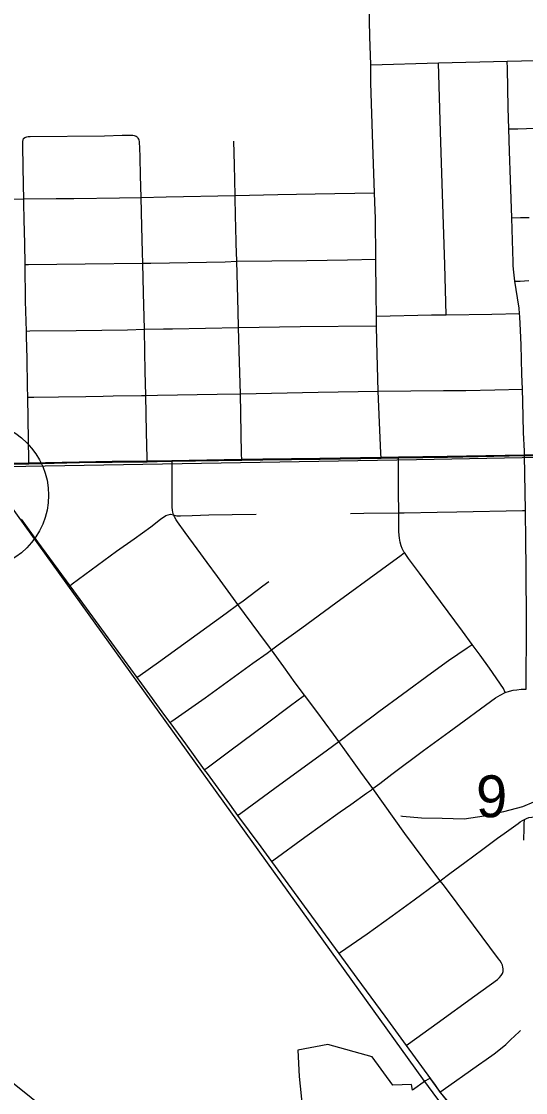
# Model space of a CAD drawing. Extents: x -6.4 to 34, y -4.2 to 22.
# Drawn here: x 3.551 to 4.056, y 15.21 to 16.282 of the extents above; entities that cross this region are included whole.
import ezdxf

# ---------------------------------------------------------------- set-up
doc = ezdxf.new("R2010")
doc.units = 0
for name, color, linetype in [('GM_X_Corporation', 7, 'Continuous'), ('GM_X_County_Road', 7, 'Continuous'), ('GM_X_Minor_River', 7, 'Continuous'), ('GM_X_Rail_Line', 7, 'Continuous'), ('GM_X_Section_Text', 7, 'Continuous'), ('GM_X_State_Route', 7, 'Continuous'), ('GM_X_Township_Road', 7, 'Continuous'), ('GM_X_Unincorporated', 7, 'Continuous')]:
    doc.layers.add(name, color=color, linetype=linetype)

msp = doc.modelspace()

# ---------------------------------------------------------------- linework, layer by layer
at = {"layer": 'GM_X_Corporation'}
msp.add_lwpolyline([(3.9465, 15.8436), (4.8102, 15.8601), (4.8285, 15.2133), (4.4185, 15.2024), (4.0324, 15.1921), (3.7019, 15.1869), (3.3086, 15.1812), (3.2389, 15.1802), (3.2231, 15.8313)], close=True, dxfattribs=at)
for points in [[(4.0637, 15.8482), (4.0545, 15.848), (3.9774, 15.8466), (3.9286, 15.8458), (3.911, 15.8456), (3.8501, 15.8447), (3.7928, 15.8438), (3.7716, 15.8435), (3.7019, 15.8423), (3.6872, 15.8421), (3.6771, 15.842), (3.6422, 15.8417), (3.6093, 15.8411), (3.5587, 15.84), (3.5102, 15.839)], [(3.5102, 15.839), (3.5587, 15.84), (3.6093, 15.8411), (3.6422, 15.8417), (3.6771, 15.842), (3.6872, 15.8421), (3.7019, 15.8423), (3.7716, 15.8435), (3.7928, 15.8438), (3.8501, 15.8447), (3.911, 15.8456), (3.9286, 15.8458), (3.9774, 15.8466), (4.0545, 15.848), (4.0637, 15.8482)], [(3.9773, 15.2021), (3.9699, 15.2114), (3.9604, 15.2247), (3.9558, 15.222), (3.9426, 15.2128), (3.9415, 15.2183), (3.9228, 15.2178), (3.9022, 15.2461), (3.8579, 15.2584), (3.828, 15.2527), (3.8293, 15.2262), (3.8325, 15.1939)]]:
    msp.add_lwpolyline(points, dxfattribs=at)
at = {"layer": 'GM_X_County_Road'}
msp.add_lwpolyline([(3.5104, 15.8384), (3.5589, 15.8394), (3.6095, 15.8405), (3.6424, 15.8411), (3.6773, 15.8414), (3.6874, 15.8415), (3.7021, 15.8418), (3.7718, 15.8429), (3.793, 15.8433), (3.8503, 15.8441), (3.9112, 15.845), (3.9288, 15.8453), (3.9776, 15.846), (4.0547, 15.8475), (4.0639, 15.8477), (4.1199, 15.8487)], dxfattribs=at)
at = {"layer": 'GM_X_Minor_River'}
msp.add_lwpolyline([(4.0745, 15.5053), (4.0528, 15.4961), (4.0335, 15.4911), (4.0143, 15.4869), (3.9943, 15.4838), (3.9723, 15.4845), (3.9518, 15.4848), (3.9325, 15.4863), (3.931, 15.4867)], dxfattribs=at)
at = {"layer": 'GM_X_Rail_Line'}
for points in [[(3.9386, 14.884), (3.8593, 14.9547), (3.8412, 14.9757), (3.7101, 15.0851), (3.4966, 15.2567), (3.3676, 15.3664), (3.3218, 15.4134), (3.2936, 15.4451), (3.262, 15.4819), (3.2273, 15.5333), (3.0474, 15.8446), (2.8972, 16.1027), (2.8207, 16.2287), (2.6643, 16.5111), (2.602, 16.6246), (2.5066, 16.7881), (2.4417, 16.9006), (2.4184, 16.9355), (2.3897, 16.999), (2.3745, 17.0469), (2.3628, 17.1053), (2.3468, 17.2127), (2.3318, 17.3221), (2.3038, 17.4809)], [(2.3038, 17.4809), (2.7191, 16.9064), (3.0546, 16.4509), (3.5178, 15.8282), (3.9525, 15.2239), (4.2793, 14.7815), (4.2857, 14.7721), (4.2939, 14.7539), (4.295, 14.5937)]]:
    msp.add_lwpolyline(points, dxfattribs=at)
at = {"layer": 'GM_X_State_Route'}
for points in [[(3.5511, 15.7838), (3.5676, 15.7612), (3.5998, 15.7173), (3.629, 15.6775), (3.667, 15.6254), (3.6715, 15.6192), (3.6946, 15.5876), (3.6999, 15.5804), (3.7156, 15.559), (3.7344, 15.5332), (3.7372, 15.5293), (3.7596, 15.4988), (3.7677, 15.4876), (3.7908, 15.4561), (3.8016, 15.4414), (3.8378, 15.3918), (3.8689, 15.3494), (3.8871, 15.3247), (3.9151, 15.2866), (3.9364, 15.2573), (3.9606, 15.2241)], [(3.9606, 15.2241), (3.9652, 15.2177), (3.9701, 15.2108), (3.9775, 15.2015)]]:
    msp.add_lwpolyline(points, dxfattribs=at)
at = {"layer": 'GM_X_Township_Road'}
msp.add_line((3.9067, 15.9775), (3.9066, 15.9871), dxfattribs=at)
for points in [[(3.9066, 15.9871), (3.9064, 16.0085), (3.9059, 16.044), (3.9055, 16.0855), (3.9053, 16.0923), (3.9047, 16.1104), (3.9044, 16.1202), (3.903, 16.1587), (3.901, 16.2204), (3.9008, 16.2386), (3.9001, 16.2669), (3.8989, 16.3134), (3.898, 16.347), (3.8977, 16.3644), (3.8972, 16.3921), (3.8969, 16.4085), (3.8965, 16.4331)], [(3.9008, 16.2386), (3.9688, 16.2404), (4.0374, 16.2421), (4.0949, 16.2434)], [(3.9762, 15.9884), (3.9751, 16.0385), (3.9725, 16.1093), (3.9708, 16.1715), (3.9688, 16.2404)], [(4.0496, 15.9898), (4.0492, 15.9949), (4.0476, 16.0054), (4.045, 16.0219), (4.0436, 16.0341), (4.0434, 16.0378), (4.0433, 16.0415), (4.0427, 16.0626), (4.042, 16.0855), (4.0406, 16.1235), (4.0397, 16.1521), (4.039, 16.1743), (4.0384, 16.1956), (4.0376, 16.2348), (4.0374, 16.2421)], [(4.039, 16.1743), (4.0481, 16.1746), (4.0654, 16.1751), (4.0826, 16.1757)], [(3.5589, 15.8394), (3.5589, 15.8426), (3.5583, 15.8844), (3.5579, 15.9059), (3.5577, 15.9166), (3.5571, 15.9448), (3.5566, 15.9668), (3.5564, 15.9721), (3.5556, 16.0021), (3.5551, 16.0387), (3.5548, 16.0596), (3.5543, 16.0835), (3.5539, 16.1001), (3.5538, 16.1043), (3.5534, 16.1182), (3.5528, 16.1563), (3.5529, 16.1618), (3.5531, 16.1636), (3.5536, 16.1649), (3.5549, 16.1659)], [(3.5549, 16.1659), (3.5569, 16.1666), (3.5583, 16.1669), (3.5602, 16.1668), (3.6346, 16.1676), (3.6522, 16.1681), (3.6591, 16.1682), (3.6613, 16.1682), (3.6629, 16.1681), (3.6641, 16.1679), (3.6652, 16.1676), (3.6663, 16.1672), (3.6671, 16.1666)], [(3.6773, 15.8414), (3.6773, 15.8448), (3.6767, 15.8711), (3.676, 15.9078), (3.6754, 15.9321), (3.675, 15.9512), (3.6745, 15.974), (3.6737, 16.0105), (3.6728, 16.04), (3.6726, 16.0507), (3.672, 16.0767), (3.6712, 16.1058), (3.6707, 16.1276), (3.6703, 16.1459), (3.6699, 16.1559), (3.6696, 16.1603), (3.6695, 16.1618), (3.6692, 16.1631), (3.6688, 16.1642), (3.6682, 16.1652), (3.6677, 16.1659), (3.6671, 16.1666)], [(3.7657, 16.0859), (3.7652, 16.1078), (3.7645, 16.1384), (3.7639, 16.1621)], [(3.3737, 16.1144), (3.381, 16.1107), (3.3882, 16.1072), (3.3921, 16.1056), (3.3974, 16.104), (3.4039, 16.1025), (3.4087, 16.1017), (3.4142, 16.1014), (3.4204, 16.1014), (3.4322, 16.1014), (3.4569, 16.102), (3.4797, 16.1026), (3.507, 16.1036), (3.5349, 16.1041), (3.5538, 16.1043), (3.5862, 16.1047), (3.6039, 16.1049), (3.6497, 16.1054), (3.6712, 16.1058), (3.6962, 16.1063), (3.7652, 16.1078), (3.8079, 16.1088), (3.8452, 16.1093), (3.9047, 16.1104)], [(3.7718, 15.8429), (3.7717, 15.8497), (3.7705, 15.9092), (3.7697, 15.941), (3.7687, 15.9756), (3.7682, 15.992), (3.7669, 16.0419), (3.7664, 16.0596), (3.7659, 16.077), (3.7657, 16.0859)], [(4.042, 16.0855), (4.0508, 16.0856), (4.0594, 16.0857)], [(3.5551, 16.0387), (3.5587, 16.0388), (3.6152, 16.0395), (3.6728, 16.04), (3.681, 16.0402), (3.7551, 16.0415), (3.7669, 16.0419), (3.8371, 16.0428), (3.8775, 16.0435), (3.9059, 16.044)], [(4.045, 16.0219), (4.0504, 16.0222), (4.059, 16.0227)], [(3.9066, 15.9871), (3.9616, 15.9882), (3.9762, 15.9884), (4.0219, 15.989), (4.0496, 15.9898)], [(4.0547, 15.8475), (4.0545, 15.8519), (4.0535, 15.8707), (4.0529, 15.9018), (4.0525, 15.9139), (4.052, 15.9291), (4.0513, 15.9583), (4.0508, 15.9726), (4.0499, 15.9863), (4.0496, 15.9898)], [(3.5564, 15.9721), (3.5598, 15.9722), (3.6063, 15.9728), (3.6576, 15.9735), (3.6745, 15.974), (3.6936, 15.9743)], [(3.6936, 15.9743), (3.7026, 15.9744), (3.7687, 15.9756), (3.8303, 15.9768), (3.9067, 15.9775)], [(3.9112, 15.845), (3.911, 15.8501), (3.9096, 15.8808), (3.9084, 15.9119), (3.9076, 15.937), (3.9069, 15.9617), (3.9067, 15.9775)], [(3.5579, 15.9059), (3.5639, 15.906), (3.5885, 15.9063), (3.6158, 15.9067), (3.6332, 15.9071), (3.6431, 15.9074), (3.6715, 15.9077), (3.676, 15.9078), (3.6877, 15.908), (3.7472, 15.9089), (3.7705, 15.9092), (3.8482, 15.9109), (3.9084, 15.9119)], [(3.9084, 15.9119), (3.9737, 15.9125), (3.996, 15.9128), (4.025, 15.9133), (4.0525, 15.9139)], [(3.9733, 15.4183), (3.9704, 15.4221), (3.9631, 15.4316), (3.935, 15.4695), (3.903, 15.5143), (3.891, 15.5308), (3.8843, 15.5401), (3.8689, 15.5614), (3.8636, 15.5687), (3.8469, 15.5914), (3.8345, 15.6079), (3.8254, 15.6202), (3.8138, 15.6363), (3.8015, 15.6531), (3.7995, 15.6558), (3.7891, 15.6701), (3.768, 15.6985), (3.7635, 15.7045), (3.7476, 15.7264), (3.7373, 15.7407), (3.7274, 15.7544), (3.7154, 15.7707), (3.7076, 15.7814), (3.7061, 15.7834), (3.7048, 15.7856), (3.7035, 15.7884), (3.7029, 15.791), (3.7025, 15.7928), (3.7023, 15.7959), (3.7022, 15.8179), (3.7021, 15.8405), (3.7021, 15.8418)], [(4.0352, 15.6105), (4.0337, 15.6144), (4.0196, 15.6348), (4.0102, 15.648), (4.0023, 15.6586), (3.9925, 15.672), (3.9564, 15.721), (3.9497, 15.7299), (3.9386, 15.7447), (3.9347, 15.7505), (3.9341, 15.7513), (3.9323, 15.7545), (3.9312, 15.7573), (3.9302, 15.7608), (3.9295, 15.765), (3.929, 15.7711), (3.9289, 15.7822), (3.9289, 15.7878), (3.9289, 15.7903), (3.9288, 15.8114), (3.9288, 15.8368), (3.9288, 15.8453)], [(4.0563, 15.614), (4.0568, 15.6793), (4.0563, 15.7357), (4.056, 15.762), (4.0555, 15.7927), (4.0547, 15.8475)], [(3.5998, 15.7173), (3.6022, 15.7191), (3.6465, 15.7519), (3.6642, 15.7644), (3.6808, 15.7764), (3.6906, 15.784), (3.6958, 15.7875), (3.6981, 15.7884), (3.7007, 15.7888), (3.7035, 15.7884)], [(3.7035, 15.7884), (3.7053, 15.7877), (3.707, 15.7873), (3.7107, 15.7871), (3.7224, 15.7876), (3.739, 15.7881), (3.7623, 15.7885), (3.7862, 15.7889)], [(3.8807, 15.7897), (3.8938, 15.7899), (3.9289, 15.7903), (3.9344, 15.7904), (3.9672, 15.7909), (3.987, 15.7912), (4.0526, 15.7926), (4.0555, 15.7927)], [(3.6999, 15.5804), (3.7018, 15.5817), (3.7351, 15.6052), (3.783, 15.6397), (3.7973, 15.65), (3.8015, 15.6531), (3.8082, 15.6582), (3.8318, 15.6753), (3.866, 15.7001), (3.9115, 15.7335), (3.9312, 15.748), (3.9347, 15.7505)], [(3.768, 15.6985), (3.7732, 15.7023), (3.7931, 15.7172), (3.799, 15.7216)], [(3.667, 15.6254), (3.6703, 15.6278), (3.6885, 15.641), (3.7561, 15.6899), (3.768, 15.6985)], [(3.7677, 15.4876), (3.7708, 15.4898), (3.8049, 15.5148), (3.8575, 15.5533), (3.8689, 15.5614), (3.8841, 15.5728), (3.9032, 15.5873), (3.9089, 15.5916), (3.9327, 15.609), (3.9616, 15.6302), (3.9786, 15.6425), (3.9974, 15.6552), (4.0023, 15.6586)], [(3.7344, 15.5332), (3.7372, 15.5352), (3.7612, 15.5531), (3.7948, 15.5781), (3.8205, 15.5974), (3.8333, 15.607), (3.8345, 15.6079)], [(3.8965, 15.5097), (3.9015, 15.5132), (3.903, 15.5143), (3.9099, 15.5193), (3.9221, 15.5287), (3.9535, 15.5526), (3.9792, 15.571), (4.0258, 15.6051), (4.0302, 15.6078), (4.0352, 15.6105), (4.0397, 15.612), (4.0433, 15.6127), (4.047, 15.6133), (4.0512, 15.6137), (4.0563, 15.614)], [(3.8016, 15.4414), (3.8038, 15.443), (3.8349, 15.4657), (3.8702, 15.4911), (3.8808, 15.4985), (3.8965, 15.5097)], [(4.0545, 15.4834), (4.0565, 15.4844), (4.0591, 15.4853), (4.0619, 15.4859), (4.0644, 15.4862), (4.07, 15.4864), (4.0814, 15.4865), (4.1248, 15.4869), (4.1547, 15.4867), (4.1602, 15.4867)], [(3.8689, 15.3494), (3.8706, 15.3506), (3.8974, 15.3691), (3.9224, 15.3871), (3.9443, 15.4031), (3.9659, 15.419), (3.9704, 15.4221), (3.98, 15.4293), (3.9949, 15.4403), (4.0129, 15.4537), (4.0278, 15.4647), (4.0342, 15.4694), (4.0483, 15.4796), (4.0504, 15.481), (4.0526, 15.4823), (4.0545, 15.4834)], [(4.0539, 15.4626), (4.054, 15.4656), (4.0542, 15.472), (4.0544, 15.4791), (4.0545, 15.4834)], [(4.0332, 15.3313), (4.0334, 15.3341), (4.0331, 15.3358), (4.0325, 15.3378), (4.0315, 15.3398), (4.0303, 15.342), (4.0288, 15.3442), (3.9786, 15.4113), (3.9733, 15.4183)], [(3.9364, 15.2573), (3.9387, 15.259), (3.9674, 15.2797), (4.005, 15.307), (4.0276, 15.3234), (4.0298, 15.3255), (4.0314, 15.3272), (4.0327, 15.3294), (4.0332, 15.3313)], [(3.9701, 15.2108), (3.9791, 15.2171), (4.0006, 15.2324), (4.0088, 15.2381), (4.0162, 15.2433), (4.0242, 15.2491), (4.0322, 15.2552), (4.0359, 15.2584), (4.0407, 15.2629), (4.0449, 15.2669), (4.0493, 15.271), (4.0506, 15.2723)]]:
    msp.add_lwpolyline(points, dxfattribs=at)
at = {"layer": 'GM_X_Unincorporated'}
msp.add_circle((3.5042, 15.8078), 0.0744, dxfattribs=at)

# ---------------------------------------------------------------- texts
at = {"layer": 'GM_X_Section_Text'}
msp.add_text('9', height=0.0419, rotation=0, dxfattribs=at).set_placement((4.0062, 15.4857))

doc.saveas('drawing.dxf')
